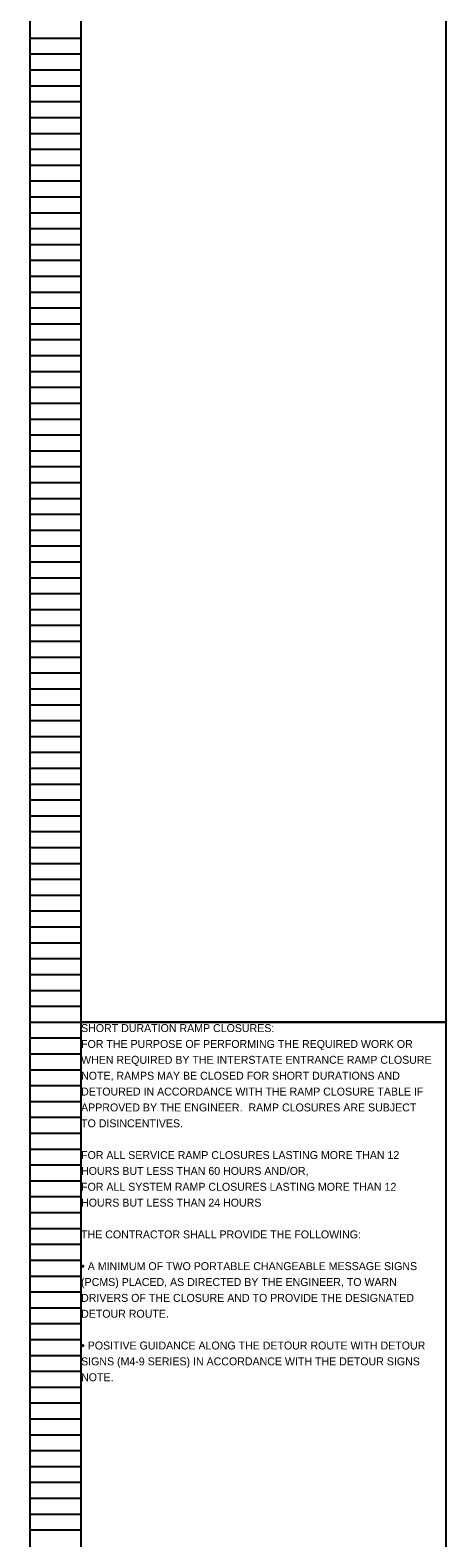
# Model space of a CAD drawing. Extents: x 16463 to 16500, y 5400 to 5823.
# Drawn here: x 16463.05 to 16470.39, y 5532.13 to 5558.73 of the extents above; entities that cross this region are included whole.
import ezdxf

# ---------------------------------------------------------------- set-up
doc = ezdxf.new("R2010")
doc.units = 0
for name, color, linetype in [('Default', 7, 'Continuous'), ('SC_Scratch1', 7, 'Continuous'), ('SH_Data', 7, 'Continuous')]:
    doc.layers.add(name, color=color, linetype=linetype)

msp = doc.modelspace()

# ---------------------------------------------------------------- linework, layer by layer
at = {"layer": 'SC_Scratch1'}
for points in [[(16463.949, 5561.392), (16470.389, 5561.392), (16470.389, 5541.232), (16463.949, 5541.232)], [(16463.949, 5541.232), (16470.389, 5541.232), (16470.389, 5521.072), (16463.949, 5521.072)]]:
    msp.add_lwpolyline(points, close=True, dxfattribs=at)
at = {"layer": 'SH_Data'}
for p, q in [((16463.049, 5541.232), (16463.049, 5561.392)), ((16463.949, 5541.232), (16463.949, 5561.392)), ((16463.049, 5558.592), (16463.949, 5558.592)), ((16463.049, 5558.312), (16463.949, 5558.312)), ((16463.049, 5558.032), (16463.949, 5558.032)), ((16463.049, 5557.752), (16463.949, 5557.752)), ((16463.049, 5557.472), (16463.949, 5557.472)), ((16463.049, 5557.192), (16463.949, 5557.192)), ((16463.049, 5556.912), (16463.949, 5556.912)), ((16463.049, 5556.632), (16463.949, 5556.632)), ((16463.049, 5556.352), (16463.949, 5556.352)), ((16463.049, 5556.072), (16463.949, 5556.072)), ((16463.049, 5555.792), (16463.949, 5555.792)), ((16463.049, 5555.512), (16463.949, 5555.512)), ((16463.049, 5555.232), (16463.949, 5555.232)), ((16463.049, 5554.952), (16463.949, 5554.952)), ((16463.049, 5554.672), (16463.949, 5554.672)), ((16463.049, 5554.392), (16463.949, 5554.392)), ((16463.049, 5554.112), (16463.949, 5554.112)), ((16463.049, 5553.832), (16463.949, 5553.832)), ((16463.049, 5553.552), (16463.949, 5553.552)), ((16463.049, 5553.272), (16463.949, 5553.272)), ((16463.049, 5552.992), (16463.949, 5552.992)), ((16463.049, 5552.712), (16463.949, 5552.712)), ((16463.049, 5552.432), (16463.949, 5552.432)), ((16463.049, 5552.152), (16463.949, 5552.152)), ((16463.049, 5551.872), (16463.949, 5551.872)), ((16463.049, 5551.592), (16463.949, 5551.592)), ((16463.049, 5551.312), (16463.949, 5551.312)), ((16463.049, 5551.032), (16463.949, 5551.032)), ((16463.049, 5550.752), (16463.949, 5550.752)), ((16463.049, 5550.472), (16463.949, 5550.472)), ((16463.049, 5550.192), (16463.949, 5550.192)), ((16463.049, 5549.912), (16463.949, 5549.912)), ((16463.049, 5549.632), (16463.949, 5549.632)), ((16463.049, 5549.352), (16463.949, 5549.352)), ((16463.049, 5549.072), (16463.949, 5549.072)), ((16463.049, 5548.792), (16463.949, 5548.792)), ((16463.049, 5548.512), (16463.949, 5548.512)), ((16463.049, 5548.232), (16463.949, 5548.232)), ((16463.049, 5547.952), (16463.949, 5547.952)), ((16463.049, 5547.672), (16463.949, 5547.672)), ((16463.049, 5547.392), (16463.949, 5547.392)), ((16463.049, 5547.112), (16463.949, 5547.112)), ((16463.049, 5546.832), (16463.949, 5546.832)), ((16463.049, 5546.552), (16463.949, 5546.552)), ((16463.049, 5546.272), (16463.949, 5546.272)), ((16463.049, 5545.992), (16463.949, 5545.992)), ((16463.049, 5545.712), (16463.949, 5545.712)), ((16463.049, 5545.432), (16463.949, 5545.432)), ((16463.049, 5545.152), (16463.949, 5545.152)), ((16463.049, 5544.872), (16463.949, 5544.872)), ((16463.049, 5544.592), (16463.949, 5544.592)), ((16463.049, 5544.312), (16463.949, 5544.312)), ((16463.049, 5544.032), (16463.949, 5544.032)), ((16463.049, 5543.752), (16463.949, 5543.752)), ((16463.049, 5543.472), (16463.949, 5543.472)), ((16463.049, 5543.192), (16463.949, 5543.192)), ((16463.049, 5542.912), (16463.949, 5542.912)), ((16463.049, 5542.632), (16463.949, 5542.632)), ((16463.049, 5542.352), (16463.949, 5542.352)), ((16463.049, 5542.072), (16463.949, 5542.072)), ((16463.049, 5541.792), (16463.949, 5541.792)), ((16463.049, 5541.512), (16463.949, 5541.512)), ((16463.049, 5521.072), (16463.049, 5541.232)), ((16463.049, 5541.232), (16463.949, 5541.232)), ((16463.049, 5541.232), (16463.949, 5541.232)), ((16463.949, 5521.072), (16463.949, 5541.232)), ((16463.049, 5540.952), (16463.949, 5540.952)), ((16463.049, 5540.672), (16463.949, 5540.672)), ((16463.049, 5540.392), (16463.949, 5540.392)), ((16463.049, 5540.112), (16463.949, 5540.112)), ((16463.049, 5539.832), (16463.949, 5539.832)), ((16463.049, 5539.552), (16463.949, 5539.552)), ((16463.049, 5539.272), (16463.949, 5539.272)), ((16463.049, 5538.992), (16463.949, 5538.992)), ((16463.049, 5538.712), (16463.949, 5538.712)), ((16463.049, 5538.432), (16463.949, 5538.432)), ((16463.049, 5538.152), (16463.949, 5538.152)), ((16463.049, 5537.872), (16463.949, 5537.872)), ((16463.049, 5537.592), (16463.949, 5537.592)), ((16463.049, 5537.312), (16463.949, 5537.312)), ((16463.049, 5537.032), (16463.949, 5537.032)), ((16463.049, 5536.752), (16463.949, 5536.752)), ((16463.049, 5536.472), (16463.949, 5536.472)), ((16463.049, 5536.192), (16463.949, 5536.192)), ((16463.049, 5535.912), (16463.949, 5535.912)), ((16463.049, 5535.632), (16463.949, 5535.632)), ((16463.049, 5535.352), (16463.949, 5535.352)), ((16463.049, 5535.072), (16463.949, 5535.072)), ((16463.049, 5534.792), (16463.949, 5534.792)), ((16463.049, 5534.512), (16463.949, 5534.512)), ((16463.049, 5534.232), (16463.949, 5534.232)), ((16463.049, 5533.952), (16463.949, 5533.952)), ((16463.049, 5533.672), (16463.949, 5533.672)), ((16463.049, 5533.392), (16463.949, 5533.392)), ((16463.049, 5533.112), (16463.949, 5533.112)), ((16463.049, 5532.832), (16463.949, 5532.832)), ((16463.049, 5532.552), (16463.949, 5532.552)), ((16463.049, 5532.272), (16463.949, 5532.272))]:
    msp.add_line(p, q, dxfattribs=at)

# ---------------------------------------------------------------- texts
at = {"layer": 'Default'}
for s, p in [('SHORT DURATION RAMP CLOSURES:', (16463.949, 5541.056)), ('FOR THE PURPOSE OF PERFORMING THE REQUIRED WORK OR ', (16463.949, 5540.776)), ('WHEN REQUIRED BY THE INTERSTATE ENTRANCE RAMP CLOSURE ', (16463.949, 5540.496)), ('NOTE, RAMPS MAY BE CLOSED FOR SHORT DURATIONS AND ', (16463.949, 5540.216)), ('DETOURED IN ACCORDANCE WITH THE RAMP CLOSURE TABLE IF ', (16463.949, 5539.936)), ('APPROVED BY THE ENGINEER.  RAMP CLOSURES ARE SUBJECT ', (16463.949, 5539.656)), ('TO DISINCENTIVES.', (16463.949, 5539.376)), ('FOR ALL SERVICE RAMP CLOSURES LASTING MORE THAN 12 ', (16463.949, 5538.816)), ('HOURS BUT LESS THAN 60 HOURS AND/OR,', (16463.949, 5538.536)), ('FOR ALL SYSTEM RAMP CLOSURES LASTING MORE THAN 12 ', (16463.949, 5538.256)), ('HOURS BUT LESS THAN 24 HOURS ', (16463.949, 5537.976)), ('THE CONTRACTOR SHALL PROVIDE THE FOLLOWING:', (16463.949, 5537.416)), ('• A MINIMUM OF TWO PORTABLE CHANGEABLE MESSAGE SIGNS ', (16463.949, 5536.856)), ('(PCMS) PLACED, AS DIRECTED BY THE ENGINEER, TO WARN ', (16463.949, 5536.576)), ('DRIVERS OF THE CLOSURE AND TO PROVIDE THE DESIGNATED ', (16463.949, 5536.296)), ('DETOUR ROUTE. ', (16463.949, 5536.016)), ('• POSITIVE GUIDANCE ALONG THE DETOUR ROUTE WITH DETOUR ', (16463.949, 5535.456)), ('SIGNS (M4-9 SERIES) IN ACCORDANCE WITH THE DETOUR SIGNS ', (16463.949, 5535.176)), ('NOTE.  ', (16463.949, 5534.896))]:
    msp.add_text(s, height=0.14, dxfattribs=at).set_placement(p)

doc.saveas('drawing.dxf')
